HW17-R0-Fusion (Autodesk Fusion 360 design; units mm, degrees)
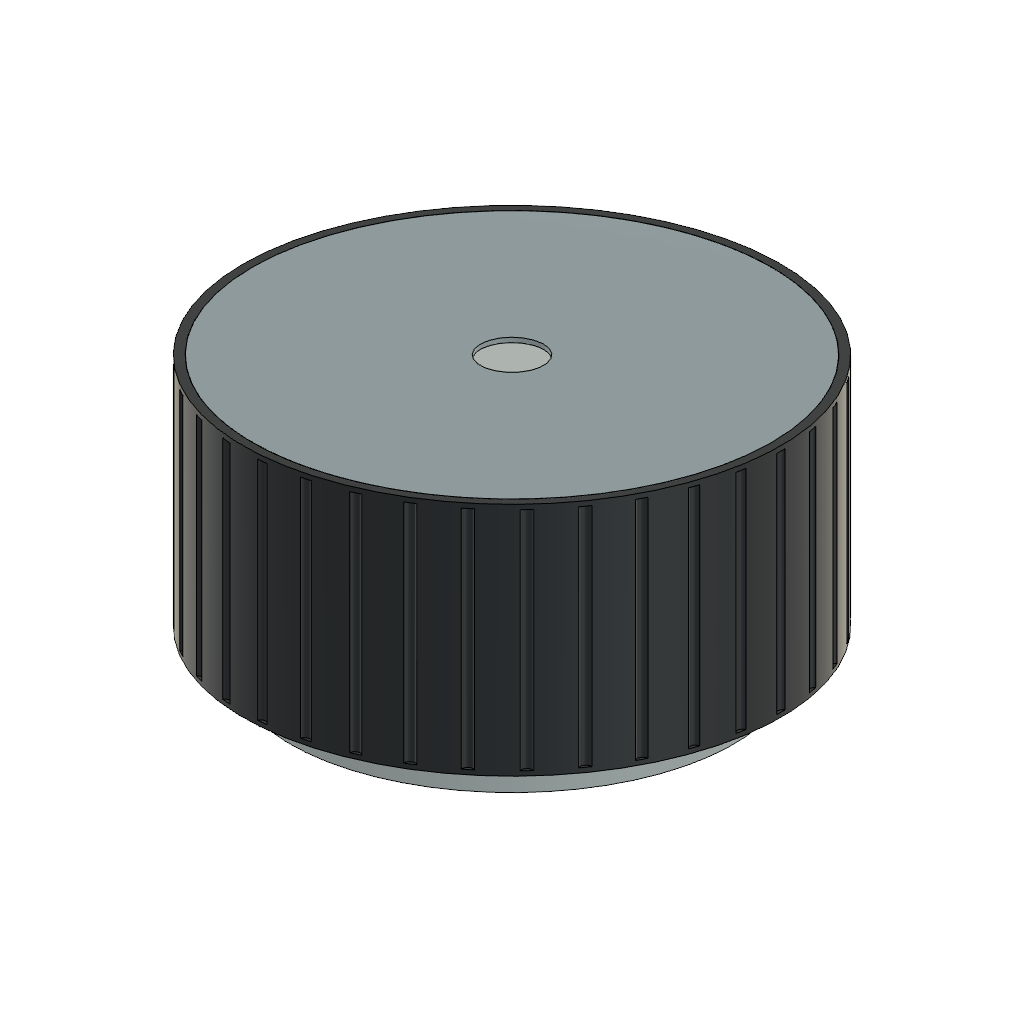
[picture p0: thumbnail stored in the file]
description: Part Number
part number: 2026-10-29-11-14-16-184
part number: 2026-10-29-11-14-16-256
part number: 2026-10-29-11-14-16-259
description: POM | 36 shallow axial flutes, max OD17; black matte finish
part number: HW17-R0-01_grip_ring
part number: HW17-R0-02_rotor_back_iron
part number: HW17-R0-03_rotor_cap
part number: HW17-R0-04_rotor_shaft
part number: HW17-R0-05_magnet_01_N
part number: HW17-R0-05_magnet_02_S
part number: HW17-R0-05_magnet_03_N
part number: HW17-R0-05_magnet_04_S
parameter "grip_od_mm" = 17 comment "R0 geometry source; see build script for dependent sketch geometry"
parameter "grip_id_mm" = 16.4 comment "R0 geometry source; see build script for dependent sketch geometry"
parameter "rotor_bottom_z_mm" = 1.2 comment "R0 geometry source; see build script for dependent sketch geometry"
parameter "top_z_mm" = 8.8 comment "R0 geometry source; see build script for dependent sketch geometry"
parameter "rotor_yoke_id_mm" = 15.4 comment "R0 geometry source; see build script for dependent sketch geometry"
parameter "rotor_yoke_top_z_mm" = 8 comment "R0 geometry source; see build script for dependent sketch geometry"
parameter "cap_spigot_od_mm" = 15.36 comment "R0 geometry source; see build script for dependent sketch geometry"
parameter "cap_spigot_id_mm" = 14 comment "R0 geometry source; see build script for dependent sketch geometry"
parameter "cap_spigot_bottom_z_mm" = 7.4 comment "R0 geometry source; see build script for dependent sketch geometry"
parameter "magnet_od_mm" = 15.3 comment "R0 geometry source; see build script for dependent sketch geometry"
parameter "magnet_id_mm" = 13.5 comment "R0 geometry source; see build script for dependent sketch geometry"
parameter "magnet_bottom_z_mm" = 2.05 comment "R0 geometry source; see build script for dependent sketch geometry"
parameter "magnet_height_mm" = 4.5 comment "R0 geometry source; see build script for dependent sketch geometry"
parameter "stator_od_mm" = 13 comment "R0 geometry source; see build script for dependent sketch geometry"
parameter "stator_id_mm" = 6.1 comment "R0 geometry source; see build script for dependent sketch geometry"
parameter "stator_yoke_od_mm" = 8 comment "R0 geometry source; see build script for dependent sketch geometry"
parameter "stator_bottom_z_mm" = 2.3 comment "R0 geometry source; see build script for dependent sketch geometry"
parameter "stator_stack_mm" = 4 comment "R0 geometry source; see build script for dependent sketch geometry"
parameter "lamination_mm" = 0.2 comment "R0 geometry source; see build script for dependent sketch geometry"
parameter "tooth_width_mm" = 0.8 comment "R0 geometry source; see build script for dependent sketch geometry"
parameter "tooth_tip_root_radius_mm" = 6.1 comment "R0 geometry source; see build script for dependent sketch geometry"
parameter "coil_r_min_mm" = 4.2 comment "R0 geometry source; see build script for dependent sketch geometry"
parameter "coil_r_max_mm" = 5.95 comment "R0 geometry source; see build script for dependent sketch geometry"
parameter "coil_half_width_mm" = 0.98 comment "R0 geometry source; see build script for dependent sketch geometry"
parameter "coil_inner_half_width_mm" = 0.5 comment "R0 geometry source; see build script for dependent sketch geometry"
parameter "coil_bottom_z_mm" = 1.72 comment "R0 geometry source; see build script for dependent sketch geometry"
parameter "coil_top_z_mm" = 6.88 comment "R0 geometry source; see build script for dependent sketch geometry"
parameter "carrier_base_od_mm" = 14 comment "R0 geometry source; see build script for dependent sketch geometry"
parameter "carrier_base_thickness_mm" = 0.6 comment "R0 geometry source; see build script for dependent sketch geometry"
parameter "carrier_post_od_mm" = 6 comment "R0 geometry source; see build script for dependent sketch geometry"
parameter "bearing_od_mm" = 5 comment "R0 geometry source; see build script for dependent sketch geometry"
parameter "bearing_id_mm" = 2 comment "R0 geometry source; see build script for dependent sketch geometry"
parameter "bearing_width_mm" = 2.5 comment "R0 geometry source; see build script for dependent sketch geometry"
parameter "bearing_lower_z_mm" = 2.7 comment "R0 geometry source; see build script for dependent sketch geometry"
parameter "bearing_upper_z_mm" = 5.3 comment "R0 geometry source; see build script for dependent sketch geometry"
parameter "bearing_outer_stop_id_mm" = 4.5 comment "R0 geometry source; see build script for dependent sketch geometry"
parameter "bearing_inner_abutment_od_mm" = 2.6 comment "R0 geometry source; see build script for dependent sketch geometry"
parameter "mount_pcd_mm" = 10.8 comment "R0 geometry source; see build script for dependent sketch geometry"
parameter "mount_boss_od_mm" = 2.4 comment "R0 geometry source; see build script for dependent sketch geometry"
parameter "mount_boss_top_z_mm" = 1.5 comment "R0 geometry source; see build script for dependent sketch geometry"
parameter "mount_pilot_diameter_mm" = 1.1 comment "R0 geometry source; see build script for dependent sketch geometry"
parameter "sensor_pcb_od_mm" = 5.5 comment "R0 geometry source; see build script for dependent sketch geometry"
parameter "sensor_pcb_thickness_mm" = 0.4 comment "R0 geometry source; see build script for dependent sketch geometry"
parameter "sensor_pocket_od_mm" = 5.6 comment "R0 geometry source; see build script for dependent sketch geometry"
parameter "sensor_solder_z_mm" = 0.05 comment "R0 geometry source; see build script for dependent sketch geometry"
parameter "sensor_magnet_od_mm" = 4 comment "R0 geometry source; see build script for dependent sketch geometry"
parameter "sensor_magnet_height_mm" = 0.5 comment "R0 geometry source; see build script for dependent sketch geometry"
parameter "sensor_magnet_bottom_z_mm" = 1.88 comment "R0 geometry source; see build script for dependent sketch geometry"
parameter "case_base_y_mm" = 2.5 comment "R0 geometry source; see build script for dependent sketch geometry"
sketch "Sketch1" plane through (0, 0, 0) normal (0, 0, 1) x axis (1, 0, 0)
  circle C1 centre (0, 0) radius 8.5
  circle C2 centre (0, 0) radius 8.2
  dimension "d50" diameter C1 = 17 (= "2 * ( grip_od_mm / 2 )")
  dimension "d51" diameter C2 = 16.4 (= "2 * ( grip_id_mm / 2 )")
extrude "Extrude1" new body sketch "Sketch1" blind 7.6 (= "top_z_mm - rotor_bottom_z_mm") from offset 1.2 (= "rotor_bottom_z_mm") bodies "01_grip_ring"
sketch "Sketch2" plane through (0, 0, 0) normal (0, 0, 1) x axis (1, 0, 0)
  circle C1 centre (8.56, 0) radius 0.18
  circle C2 centre (8.43, 1.4864) radius 0.18
  circle C3 centre (8.0438, 2.9277) radius 0.18
  circle C4 centre (7.4132, 4.28) radius 0.18
  circle C5 centre (6.5573, 5.5023) radius 0.18
  circle C6 centre (5.5023, 6.5573) radius 0.18
  circle C7 centre (4.28, 7.4132) radius 0.18
  circle C8 centre (2.9277, 8.0438) radius 0.18
  circle C9 centre (1.4864, 8.43) radius 0.18
  circle C10 centre (0, 8.56) radius 0.18
  circle C11 centre (-1.4864, 8.43) radius 0.18
  circle C12 centre (-2.9277, 8.0438) radius 0.18
  circle C13 centre (-4.28, 7.4132) radius 0.18
  circle C14 centre (-5.5023, 6.5573) radius 0.18
  circle C15 centre (-6.5573, 5.5023) radius 0.18
  circle C16 centre (-7.4132, 4.28) radius 0.18
  circle C17 centre (-8.0438, 2.9277) radius 0.18
  circle C18 centre (-8.43, 1.4864) radius 0.18
  circle C19 centre (-8.56, 0) radius 0.18
  circle C20 centre (-8.43, -1.4864) radius 0.18
  circle C21 centre (-8.0438, -2.9277) radius 0.18
  circle C22 centre (-7.4132, -4.28) radius 0.18
  circle C23 centre (-6.5573, -5.5023) radius 0.18
  circle C24 centre (-5.5023, -6.5573) radius 0.18
  circle C25 centre (-4.28, -7.4132) radius 0.18
  circle C26 centre (-2.9277, -8.0438) radius 0.18
  circle C27 centre (-1.4864, -8.43) radius 0.18
  circle C28 centre (0, -8.56) radius 0.18
  circle C29 centre (1.4864, -8.43) radius 0.18
  circle C30 centre (2.9277, -8.0438) radius 0.18
  circle C31 centre (4.28, -7.4132) radius 0.18
  circle C32 centre (5.5023, -6.5573) radius 0.18
  circle C33 centre (6.5573, -5.5023) radius 0.18
  circle C34 centre (7.4132, -4.28) radius 0.18
  circle C35 centre (8.0438, -2.9277) radius 0.18
  circle C36 centre (8.43, -1.4864) radius 0.18
extrude "Extrude2" cut sketch "Sketch2" blind 7.3 from offset 1.35
place_component sketch "Sketch1"
sketch "Sketch1" plane through (0, 0, 0) normal (0, 0, 1) x axis (1, 0, 0)
  circle C1 centre (0, 0) radius 8.2
  circle C2 centre (0, 0) radius 7.7
  dimension "d58" diameter C1 = 16.4 (= "2 * ( grip_id_mm / 2 )")
  dimension "d59" diameter C2 = 15.4 (= "2 * ( rotor_yoke_id_mm / 2 )")
extrude "Extrude1" new body sketch "Sketch1" blind 6.8 (= "rotor_yoke_top_z_mm - rotor_bottom_z_mm") from offset 1.2 (= "rotor_bottom_z_mm") bodies "02_rotor_back_iron"
sketch "Sketch1" plane through (0, 0, 0) normal (0, 0, 1) x axis (1, 0, 0)
  circle C1 centre (0, 0) radius 8.2
  circle C2 centre (0, 0) radius 1
  dimension "d63" diameter C1 = 16.4 (= "2 * ( grip_id_mm / 2 )")
  dimension "d64" diameter C2 = 2 (= "2 * ( bearing_id_mm / 2 )")
extrude "Extrude1" new body sketch "Sketch1" blind 0.8 (= "top_z_mm - rotor_yoke_top_z_mm") from offset 8 (= "rotor_yoke_top_z_mm") bodies "03_rotor_cap"
sketch "Sketch2" plane through (0, 0, 0) normal (0, 0, 1) x axis (1, 0, 0)
  circle C1 centre (0, 0) radius 7.68
  circle C2 centre (0, 0) radius 7
  dimension "d68" diameter C1 = 15.36 (= "2 * ( cap_spigot_od_mm / 2 )")
  dimension "d69" diameter C2 = 14 (= "2 * ( cap_spigot_id_mm / 2 )")
extrude "Extrude2" add sketch "Sketch2" blind 0.6 (= "rotor_yoke_top_z_mm - cap_spigot_bottom_z_mm") from offset 7.4 (= "cap_spigot_bottom_z_mm")
sketch "Sketch3" plane through (0, 0, 0) normal (0, 0, 1) x axis (1, 0, 0)
  circle C1 centre (0, 0) radius 1.3
  circle C2 centre (0, 0) radius 1
  dimension "d73" diameter C1 = 2.6 (= "2 * ( bearing_inner_abutment_od_mm / 2 )")
  dimension "d74" diameter C2 = 2 (= "2 * ( bearing_id_mm / 2 )")
extrude "Extrude3" add sketch "Sketch3" blind 0.2 (= "rotor_yoke_top_z_mm - bearing_upper_z_mm - bearing_width_mm") from offset 7.8 (= "bearing_upper_z_mm + bearing_width_mm")
sketch "Sketch4" plane through (0, 0, 0) normal (0, 0, 1) x axis (1, 0, 0)
  circle C1 centre (0, 0) radius 3.2
  circle C2 centre (0, 0) radius 1.4
extrude "Extrude4" cut sketch "Sketch4" blind 0.31 from offset 7.79
sketch "Sketch1" plane through (0, 0, 0) normal (0, 0, 1) x axis (1, 0, 0)
  circle C1 centre (0, 0) radius 1
  dimension "d81" diameter C1 = 2 (= "2 * ( bearing_id_mm / 2 )")
extrude "Extrude1" new body sketch "Sketch1" blind 5.95 (= "top_z_mm - 0.15 mm - bearing_lower_z_mm") from offset 2.7 (= "bearing_lower_z_mm") bodies "04_rotor_shaft"
sketch "Sketch2" plane through (0, 0, 0) normal (0, 0, 1) x axis (1, 0, 0)
  circle C1 centre (0, 0) radius 1.3
  dimension "d85" diameter C1 = 2.6 (= "2 * ( bearing_inner_abutment_od_mm / 2 )")
extrude "Extrude2" add sketch "Sketch2" blind 0.3 from offset 2.4 (= "bearing_lower_z_mm - 0.3 mm")
place_component sketch "Sketch1"
sketch "Sketch1" plane through (0, 0, 0) normal (0, 0, 1) x axis (1, 0, 0)
  line L1 (6.5885, -1.4675) -> (7.467, -1.6632)
  line L2 (6.5885, 1.4675) -> (7.467, 1.6632)
  arc A1 centre (0, 0) radius 7.65 clockwise from (7.467, 1.6632) to (7.467, -1.6632)
  arc A2 centre (0, 0) radius 6.75 clockwise from (6.5885, 1.4675) to (6.5885, -1.4675)
extrude "Extrude1" new body sketch "Sketch1" blind 4.5 (= "magnet_height_mm") from offset 2.05 (= "magnet_bottom_z_mm") bodies "05_magnet_01_N"
place_component sketch "Sketch1"
sketch "Sketch1" plane through (0, 0, 0) normal (0, 0, 1) x axis (1, 0, 0)
  line L1 (6.5728, 1.5365) -> (7.4492, 1.7413)
  line L2 (5.2993, 4.1809) -> (6.0059, 4.7383)
  arc A1 centre (0, 0) radius 7.65 clockwise from (6.0059, 4.7383) to (7.4492, 1.7413)
  arc A2 centre (0, 0) radius 6.75 clockwise from (5.2993, 4.1809) to (6.5728, 1.5365)
extrude "Extrude1" new body sketch "Sketch1" blind 4.5 (= "magnet_height_mm") from offset 2.05 (= "magnet_bottom_z_mm") bodies "05_magnet_02_S"
place_component sketch "Sketch1"
sketch "Sketch1" plane through (0, 0, 0) normal (0, 0, 1) x axis (1, 0, 0)
  line L1 (5.2553, 4.2361) -> (5.956, 4.8009)
  line L2 (2.9605, 6.0661) -> (3.3553, 6.8749)
  arc A1 centre (0, 0) radius 7.65 clockwise from (3.3553, 6.8749) to (5.956, 4.8009)
  arc A2 centre (0, 0) radius 6.75 clockwise from (2.9605, 6.0661) to (5.2553, 4.2361)
extrude "Extrude1" new body sketch "Sketch1" blind 4.5 (= "magnet_height_mm") from offset 2.05 (= "magnet_bottom_z_mm") bodies "05_magnet_03_N"
place_component sketch "Sketch1"
sketch "Sketch1" plane through (0, 0, 0) normal (0, 0, 1) x axis (1, 0, 0)
  line L1 (2.8968, 6.0968) -> (3.2831, 6.9097)
  line L2 (0.0353, 6.7499) -> (0.0401, 7.6499)
  arc A1 centre (0, 0) radius 7.65 clockwise from (0.0401, 7.6499) to (3.2831, 6.9097)
  arc A2 centre (0, 0) radius 6.75 clockwise from (0.0353, 6.7499) to (2.8968, 6.0968)
extrude "Extrude1" new body sketch "Sketch1" blind 4.5 (= "magnet_height_mm") from offset 2.05 (= "magnet_bottom_z_mm") bodies "05_magnet_04_S"
place_component sketch "Sketch1"
sketch "Sketch1" plane through (0, 0, 0) normal (0, 0, 1) x axis (1, 0, 0)
  line L1 (-0.0353, 6.7499) -> (-0.0401, 7.6499)
  line L2 (-2.8968, 6.0968) -> (-3.2831, 6.9097)
  arc A1 centre (0, 0) radius 7.65 clockwise from (-3.2831, 6.9097) to (-0.0401, 7.6499)
  arc A2 centre (0, 0) radius 6.75 clockwise from (-2.8968, 6.0968) to (-0.0353, 6.7499)
extrude "Extrude1" new body sketch "Sketch1" blind 4.5 (= "magnet_height_mm") from offset 2.05 (= "magnet_bottom_z_mm") bodies "05_magnet_05_N"
place_component sketch "Sketch1"
sketch "Sketch1" plane through (0, 0, 0) normal (0, 0, 1) x axis (1, 0, 0)
  line L1 (-2.9605, 6.0661) -> (-3.3553, 6.8749)
  line L2 (-5.2553, 4.2361) -> (-5.956, 4.8009)
  arc A1 centre (0, 0) radius 7.65 clockwise from (-5.956, 4.8009) to (-3.3553, 6.8749)
  arc A2 centre (0, 0) radius 6.75 clockwise from (-5.2553, 4.2361) to (-2.9605, 6.0661)
extrude "Extrude1" new body sketch "Sketch1" blind 4.5 (= "magnet_height_mm") from offset 2.05 (= "magnet_bottom_z_mm") bodies "05_magnet_06_S"
place_component sketch "Sketch1"
sketch "Sketch1" plane through (0, 0, 0) normal (0, 0, 1) x axis (1, 0, 0)
  line L1 (-5.2993, 4.1809) -> (-6.0059, 4.7383)
  line L2 (-6.5728, 1.5365) -> (-7.4492, 1.7413)
  arc A1 centre (0, 0) radius 7.65 clockwise from (-7.4492, 1.7413) to (-6.0059, 4.7383)
  arc A2 centre (0, 0) radius 6.75 clockwise from (-6.5728, 1.5365) to (-5.2993, 4.1809)
extrude "Extrude1" new body sketch "Sketch1" blind 4.5 (= "magnet_height_mm") from offset 2.05 (= "magnet_bottom_z_mm") bodies "05_magnet_07_N"
place_component sketch "Sketch1"
sketch "Sketch1" plane through (0, 0, 0) normal (0, 0, 1) x axis (1, 0, 0)
  line L1 (-6.5885, 1.4675) -> (-7.467, 1.6632)
  line L2 (-6.5885, -1.4675) -> (-7.467, -1.6632)
  arc A1 centre (0, 0) radius 7.65 clockwise from (-7.467, -1.6632) to (-7.467, 1.6632)
  arc A2 centre (0, 0) radius 6.75 clockwise from (-6.5885, -1.4675) to (-6.5885, 1.4675)
extrude "Extrude1" new body sketch "Sketch1" blind 4.5 (= "magnet_height_mm") from offset 2.05 (= "magnet_bottom_z_mm") bodies "05_magnet_08_S"
place_component sketch "Sketch1"
sketch "Sketch1" plane through (0, 0, 0) normal (0, 0, 1) x axis (1, 0, 0)
  line L1 (-6.5728, -1.5365) -> (-7.4492, -1.7413)
  line L2 (-5.2993, -4.1809) -> (-6.0059, -4.7383)
  arc A1 centre (0, 0) radius 7.65 clockwise from (-6.0059, -4.7383) to (-7.4492, -1.7413)
  arc A2 centre (0, 0) radius 6.75 clockwise from (-5.2993, -4.1809) to (-6.5728, -1.5365)
extrude "Extrude1" new body sketch "Sketch1" blind 4.5 (= "magnet_height_mm") from offset 2.05 (= "magnet_bottom_z_mm") bodies "05_magnet_09_N"
place_component sketch "Sketch1"
sketch "Sketch1" plane through (0, 0, 0) normal (0, 0, 1) x axis (1, 0, 0)
  line L1 (-5.2553, -4.2361) -> (-5.956, -4.8009)
  line L2 (-2.9605, -6.0661) -> (-3.3553, -6.8749)
  arc A1 centre (0, 0) radius 7.65 clockwise from (-3.3553, -6.8749) to (-5.956, -4.8009)
  arc A2 centre (0, 0) radius 6.75 clockwise from (-2.9605, -6.0661) to (-5.2553, -4.2361)
extrude "Extrude1" new body sketch "Sketch1" blind 4.5 (= "magnet_height_mm") from offset 2.05 (= "magnet_bottom_z_mm") bodies "05_magnet_10_S"
place_component sketch "Sketch1"
sketch "Sketch1" plane through (0, 0, 0) normal (0, 0, 1) x axis (1, 0, 0)
  line L1 (-2.8968, -6.0968) -> (-3.2831, -6.9097)
  line L2 (-0.0353, -6.7499) -> (-0.0401, -7.6499)
  arc A1 centre (0, 0) radius 7.65 clockwise from (-0.0401, -7.6499) to (-3.2831, -6.9097)
  arc A2 centre (0, 0) radius 6.75 clockwise from (-0.0353, -6.7499) to (-2.8968, -6.0968)
extrude "Extrude1" new body sketch "Sketch1" blind 4.5 (= "magnet_height_mm") from offset 2.05 (= "magnet_bottom_z_mm") bodies "05_magnet_11_N"
place_component sketch "Sketch1"
sketch "Sketch1" plane through (0, 0, 0) normal (0, 0, 1) x axis (1, 0, 0)
  line L1 (0.0353, -6.7499) -> (0.0401, -7.6499)
  line L2 (2.8968, -6.0968) -> (3.2831, -6.9097)
  arc A1 centre (0, 0) radius 7.65 clockwise from (3.2831, -6.9097) to (0.0401, -7.6499)
  arc A2 centre (0, 0) radius 6.75 clockwise from (2.8968, -6.0968) to (0.0353, -6.7499)
extrude "Extrude1" new body sketch "Sketch1" blind 4.5 (= "magnet_height_mm") from offset 2.05 (= "magnet_bottom_z_mm") bodies "05_magnet_12_S"
place_component sketch "Sketch1"
sketch "Sketch1" plane through (0, 0, 0) normal (0, 0, 1) x axis (1, 0, 0)
  line L1 (2.9605, -6.0661) -> (3.3553, -6.8749)
  line L2 (5.2553, -4.2361) -> (5.956, -4.8009)
  arc A1 centre (0, 0) radius 7.65 clockwise from (5.956, -4.8009) to (3.3553, -6.8749)
  arc A2 centre (0, 0) radius 6.75 clockwise from (5.2553, -4.2361) to (2.9605, -6.0661)
extrude "Extrude1" new body sketch "Sketch1" blind 4.5 (= "magnet_height_mm") from offset 2.05 (= "magnet_bottom_z_mm") bodies "05_magnet_13_N"
place_component sketch "Sketch1"
sketch "Sketch1" plane through (0, 0, 0) normal (0, 0, 1) x axis (1, 0, 0)
  line L1 (5.2993, -4.1809) -> (6.0059, -4.7383)
  line L2 (6.5728, -1.5365) -> (7.4492, -1.7413)
  arc A1 centre (0, 0) radius 7.65 clockwise from (7.4492, -1.7413) to (6.0059, -4.7383)
  arc A2 centre (0, 0) radius 6.75 clockwise from (6.5728, -1.5365) to (5.2993, -4.1809)
extrude "Extrude1" new body sketch "Sketch1" blind 4.5 (= "magnet_height_mm") from offset 2.05 (= "magnet_bottom_z_mm") bodies "05_magnet_14_S"
sketch "Sketch1" plane through (0, 0, 0) normal (0, 0, 1) x axis (1, 0, 0)
  circle C1 centre (0, 0) radius 7
  dimension "d131" diameter C1 = 14 (= "2 * ( carrier_base_od_mm / 2 )")
extrude "Extrude1" new body sketch "Sketch1" along normal blind 0.6 (= "carrier_base_thickness_mm") bodies "06_stator_carrier"
sketch "Sketch2" plane through (0, 0, 0) normal (0, 0, 1) x axis (1, 0, 0)
  circle C1 centre (0, 0) radius 2.8
  dimension "d135" diameter C1 = 5.6 (= "2 * ( sensor_pocket_od_mm / 2 )")
extrude "Extrude2" cut sketch "Sketch2" blind 0.41 (= "sensor_pcb_thickness_mm + 0.01 mm") from offset -0.01
sketch "Sketch3" plane through (0, 0, 0) normal (0, 0, 1) x axis (1, 0, 0)
  circle C1 centre (0, 0) radius 2.5
  dimension "d139" diameter C1 = 5 (= "2 * ( bearing_od_mm / 2 )")
extrude "Extrude3" cut sketch "Sketch3" blind 0.21 (= "carrier_base_thickness_mm - sensor_pcb_thickness_mm + 0.01 mm") from offset 0.4 (= "sensor_pcb_thickness_mm")
sketch "Sketch4" plane through (0, 0, 0) normal (0, 0, 1) x axis (1, 0, 0)
  circle C1 centre (0, 0) radius 3
  circle C2 centre (0, 0) radius 2.5
  dimension "d143" diameter C1 = 6 (= "2 * ( carrier_post_od_mm / 2 )")
  dimension "d144" diameter C2 = 5 (= "2 * ( bearing_od_mm / 2 )")
extrude "Extrude4" add sketch "Sketch4" blind 7.2 (= "bearing_upper_z_mm + bearing_width_mm - carrier_base_thickness_mm") from offset 0.6 (= "carrier_base_thickness_mm")
sketch "Sketch5" plane through (0, 0, 0) normal (0, 0, 1) x axis (1, 0, 0)
  circle C1 centre (0, 0) radius 2.5
  circle C2 centre (0, 0) radius 2.25
  dimension "d148" diameter C1 = 5 (= "2 * ( bearing_od_mm / 2 )")
  dimension "d149" diameter C2 = 4.5 (= "2 * ( bearing_outer_stop_id_mm / 2 )")
extrude "Extrude5" add sketch "Sketch5" blind 0.1 (= "bearing_upper_z_mm - bearing_lower_z_mm - bearing_width_mm") from offset 5.2 (= "bearing_lower_z_mm + bearing_width_mm")
sketch "Sketch6" plane through (0, 0, 0) normal (0, 0, 1) x axis (1, 0, 0)
  circle C1 centre (4.6765, 2.7) radius 1.2
  dimension "d153" diameter C1 = 2.4 (= "2 * ( mount_boss_od_mm / 2 )")
extrude "Extrude6" add sketch "Sketch6" blind 0.9 (= "mount_boss_top_z_mm - carrier_base_thickness_mm") from offset 0.6 (= "carrier_base_thickness_mm")
sketch "Sketch7" plane through (0, 0, 0) normal (0, 0, 1) x axis (1, 0, 0)
  circle C1 centre (4.6765, 2.7) radius 0.55
  dimension "d157" diameter C1 = 1.1 (= "2 * ( mount_pilot_diameter_mm / 2 )")
extrude "Extrude7" cut sketch "Sketch7" blind 1.26 (= "mount_boss_top_z_mm - 0.24 mm") from offset -0.01
sketch "Sketch8" plane through (0, 0, 0) normal (0, 0, 1) x axis (1, 0, 0)
  circle C1 centre (-4.6765, 2.7) radius 1.2
  dimension "d161" diameter C1 = 2.4 (= "2 * ( mount_boss_od_mm / 2 )")
extrude "Extrude8" add sketch "Sketch8" blind 0.9 (= "mount_boss_top_z_mm - carrier_base_thickness_mm") from offset 0.6 (= "carrier_base_thickness_mm")
sketch "Sketch9" plane through (0, 0, 0) normal (0, 0, 1) x axis (1, 0, 0)
  circle C1 centre (-4.6765, 2.7) radius 0.55
  dimension "d165" diameter C1 = 1.1 (= "2 * ( mount_pilot_diameter_mm / 2 )")
extrude "Extrude9" cut sketch "Sketch9" blind 1.26 (= "mount_boss_top_z_mm - 0.24 mm") from offset -0.01
sketch "Sketch10" plane through (0, 0, 0) normal (0, 0, 1) x axis (1, 0, 0)
  circle C1 centre (0, -5.4) radius 1.2
  dimension "d169" diameter C1 = 2.4 (= "2 * ( mount_boss_od_mm / 2 )")
extrude "Extrude10" add sketch "Sketch10" blind 0.9 (= "mount_boss_top_z_mm - carrier_base_thickness_mm") from offset 0.6 (= "carrier_base_thickness_mm")
sketch "Sketch11" plane through (0, 0, 0) normal (0, 0, 1) x axis (1, 0, 0)
  circle C1 centre (0, -5.4) radius 0.55
  dimension "d173" diameter C1 = 1.1 (= "2 * ( mount_pilot_diameter_mm / 2 )")
extrude "Extrude11" cut sketch "Sketch11" blind 1.26 (= "mount_boss_top_z_mm - 0.24 mm") from offset -0.01
sketch "Sketch12" plane through (0, 0, 0) normal (0, 0, 1) x axis (1, 0, 0)
  line L1 (-4.3134, 5.7276) -> (0.7071, 0.7071)
  line L2 (-5.7276, 4.3134) -> (-4.3134, 5.7276)
  line L3 (-0.7071, -0.7071) -> (-5.7276, 4.3134)
  line L4 (0.7071, 0.7071) -> (-0.7071, -0.7071)
extrude "Extrude12" cut sketch "Sketch12" along normal blind 0.4
sketch "Sketch13" plane through (0, 0, 0) normal (0, 0, 1) x axis (1, 0, 0)
  circle C1 centre (0, 4.7) radius 0.45
extrude "Extrude13" cut sketch "Sketch13" blind 0.62 from offset -0.01
sketch "Sketch1" plane through (0, 0, 0) normal (0, 0, 1) x axis (1, 0, 0)
  circle C1 centre (0, 0) radius 4
  circle C2 centre (0, 0) radius 3.05
  dimension "d183" diameter C1 = 8 (= "2 * ( stator_yoke_od_mm / 2 )")
  dimension "d184" diameter C2 = 6.1 (= "2 * ( stator_id_mm / 2 )")
extrude "Extrude1" new body sketch "Sketch1" blind 4 (= "stator_stack_mm") from offset 2.3 (= "stator_bottom_z_mm") bodies "07_stator_stack"
sketch "Sketch2" plane through (0, 0, 0) normal (0, 0, 1) x axis (1, 0, 0)
  line L1 (6.15, -0.4) -> (3.9, -0.4)
  line L2 (6.15, 0.4) -> (6.15, -0.4)
  line L3 (3.9, 0.4) -> (6.15, 0.4)
  line L4 (3.9, -0.4) -> (3.9, 0.4)
extrude "Extrude2" add sketch "Sketch2" blind 4 (= "stator_stack_mm") from offset 2.3 (= "stator_bottom_z_mm")
sketch "Sketch3" plane through (0, 0, 0) normal (0, 0, 1) x axis (1, 0, 0)
  line L1 (5.9879, -1.1639) -> (6.3806, -1.2403)
  line L2 (5.9879, 1.1639) -> (6.3806, 1.2403)
  arc A1 centre (0, 0) radius 6.5 clockwise from (6.3806, 1.2403) to (6.3806, -1.2403)
  arc A2 centre (0, 0) radius 6.1 clockwise from (5.9879, 1.1639) to (5.9879, -1.1639)
extrude "Extrude3" add sketch "Sketch3" blind 4 (= "stator_stack_mm") from offset 2.3 (= "stator_bottom_z_mm")
sketch "Sketch4" plane through (0, 0, 0) normal (0, 0, 1) x axis (1, 0, 0)
  line L1 (5.5261, 2.7286) -> (3.5775, 1.6036)
  line L2 (5.1261, 3.4214) -> (5.5261, 2.7286)
  line L3 (3.1775, 2.2964) -> (5.1261, 3.4214)
  line L4 (3.5775, 1.6036) -> (3.1775, 2.2964)
extrude "Extrude4" add sketch "Sketch4" blind 4 (= "stator_stack_mm") from offset 2.3 (= "stator_bottom_z_mm")
sketch "Sketch5" plane through (0, 0, 0) normal (0, 0, 1) x axis (1, 0, 0)
  line L1 (5.7677, 1.986) -> (6.1459, 2.1162)
  line L2 (4.6037, 4.002) -> (4.9056, 4.2644)
  arc A1 centre (0, 0) radius 6.5 clockwise from (4.9056, 4.2644) to (6.1459, 2.1162)
  arc A2 centre (0, 0) radius 6.1 clockwise from (4.6037, 4.002) to (5.7677, 1.986)
extrude "Extrude5" add sketch "Sketch5" blind 4 (= "stator_stack_mm") from offset 2.3 (= "stator_bottom_z_mm")
sketch "Sketch6" plane through (0, 0, 0) normal (0, 0, 1) x axis (1, 0, 0)
  line L1 (3.4214, 5.1261) -> (2.2964, 3.1775)
  line L2 (2.7286, 5.5261) -> (3.4214, 5.1261)
  line L3 (1.6036, 3.5775) -> (2.7286, 5.5261)
  line L4 (2.2964, 3.1775) -> (1.6036, 3.5775)
extrude "Extrude6" add sketch "Sketch6" blind 4 (= "stator_stack_mm") from offset 2.3 (= "stator_bottom_z_mm")
sketch "Sketch7" plane through (0, 0, 0) normal (0, 0, 1) x axis (1, 0, 0)
  line L1 (4.002, 4.6037) -> (4.2644, 4.9056)
  line L2 (1.986, 5.7677) -> (2.1162, 6.1459)
  arc A1 centre (0, 0) radius 6.5 clockwise from (2.1162, 6.1459) to (4.2644, 4.9056)
  arc A2 centre (0, 0) radius 6.1 clockwise from (1.986, 5.7677) to (4.002, 4.6037)
extrude "Extrude7" add sketch "Sketch7" blind 4 (= "stator_stack_mm") from offset 2.3 (= "stator_bottom_z_mm")
sketch "Sketch8" plane through (0, 0, 0) normal (0, 0, 1) x axis (1, 0, 0)
  line L1 (0.4, 6.15) -> (0.4, 3.9)
  line L2 (-0.4, 6.15) -> (0.4, 6.15)
  line L3 (-0.4, 3.9) -> (-0.4, 6.15)
  line L4 (0.4, 3.9) -> (-0.4, 3.9)
extrude "Extrude8" add sketch "Sketch8" blind 4 (= "stator_stack_mm") from offset 2.3 (= "stator_bottom_z_mm")
sketch "Sketch9" plane through (0, 0, 0) normal (0, 0, 1) x axis (1, 0, 0)
  line L1 (1.1639, 5.9879) -> (1.2403, 6.3806)
  line L2 (-1.1639, 5.9879) -> (-1.2403, 6.3806)
  arc A1 centre (0, 0) radius 6.5 clockwise from (-1.2403, 6.3806) to (1.2403, 6.3806)
  arc A2 centre (0, 0) radius 6.1 clockwise from (-1.1639, 5.9879) to (1.1639, 5.9879)
extrude "Extrude9" add sketch "Sketch9" blind 4 (= "stator_stack_mm") from offset 2.3 (= "stator_bottom_z_mm")
sketch "Sketch10" plane through (0, 0, 0) normal (0, 0, 1) x axis (1, 0, 0)
  line L1 (-2.7286, 5.5261) -> (-1.6036, 3.5775)
  line L2 (-3.4214, 5.1261) -> (-2.7286, 5.5261)
  line L3 (-2.2964, 3.1775) -> (-3.4214, 5.1261)
  line L4 (-1.6036, 3.5775) -> (-2.2964, 3.1775)
extrude "Extrude10" add sketch "Sketch10" blind 4 (= "stator_stack_mm") from offset 2.3 (= "stator_bottom_z_mm")
sketch "Sketch11" plane through (0, 0, 0) normal (0, 0, 1) x axis (1, 0, 0)
  line L1 (-1.986, 5.7677) -> (-2.1162, 6.1459)
  line L2 (-4.002, 4.6037) -> (-4.2644, 4.9056)
  arc A1 centre (0, 0) radius 6.5 clockwise from (-4.2644, 4.9056) to (-2.1162, 6.1459)
  arc A2 centre (0, 0) radius 6.1 clockwise from (-4.002, 4.6037) to (-1.986, 5.7677)
extrude "Extrude11" add sketch "Sketch11" blind 4 (= "stator_stack_mm") from offset 2.3 (= "stator_bottom_z_mm")
sketch "Sketch12" plane through (0, 0, 0) normal (0, 0, 1) x axis (1, 0, 0)
  line L1 (-5.1261, 3.4214) -> (-3.1775, 2.2964)
  line L2 (-5.5261, 2.7286) -> (-5.1261, 3.4214)
  line L3 (-3.5775, 1.6036) -> (-5.5261, 2.7286)
  line L4 (-3.1775, 2.2964) -> (-3.5775, 1.6036)
extrude "Extrude12" add sketch "Sketch12" blind 4 (= "stator_stack_mm") from offset 2.3 (= "stator_bottom_z_mm")
sketch "Sketch13" plane through (0, 0, 0) normal (0, 0, 1) x axis (1, 0, 0)
  line L1 (-4.6037, 4.002) -> (-4.9056, 4.2644)
  line L2 (-5.7677, 1.986) -> (-6.1459, 2.1162)
  arc A1 centre (0, 0) radius 6.5 clockwise from (-6.1459, 2.1162) to (-4.9056, 4.2644)
  arc A2 centre (0, 0) radius 6.1 clockwise from (-5.7677, 1.986) to (-4.6037, 4.002)
extrude "Extrude13" add sketch "Sketch13" blind 4 (= "stator_stack_mm") from offset 2.3 (= "stator_bottom_z_mm")
sketch "Sketch14" plane through (0, 0, 0) normal (0, 0, 1) x axis (1, 0, 0)
  line L1 (-6.15, 0.4) -> (-3.9, 0.4)
  line L2 (-6.15, -0.4) -> (-6.15, 0.4)
  line L3 (-3.9, -0.4) -> (-6.15, -0.4)
  line L4 (-3.9, 0.4) -> (-3.9, -0.4)
extrude "Extrude14" add sketch "Sketch14" blind 4 (= "stator_stack_mm") from offset 2.3 (= "stator_bottom_z_mm")
sketch "Sketch15" plane through (0, 0, 0) normal (0, 0, 1) x axis (1, 0, 0)
  line L1 (-5.9879, 1.1639) -> (-6.3806, 1.2403)
  line L2 (-5.9879, -1.1639) -> (-6.3806, -1.2403)
  arc A1 centre (0, 0) radius 6.5 clockwise from (-6.3806, -1.2403) to (-6.3806, 1.2403)
  arc A2 centre (0, 0) radius 6.1 clockwise from (-5.9879, -1.1639) to (-5.9879, 1.1639)
extrude "Extrude15" add sketch "Sketch15" blind 4 (= "stator_stack_mm") from offset 2.3 (= "stator_bottom_z_mm")
sketch "Sketch16" plane through (0, 0, 0) normal (0, 0, 1) x axis (1, 0, 0)
  line L1 (-5.5261, -2.7286) -> (-3.5775, -1.6036)
  line L2 (-5.1261, -3.4214) -> (-5.5261, -2.7286)
  line L3 (-3.1775, -2.2964) -> (-5.1261, -3.4214)
  line L4 (-3.5775, -1.6036) -> (-3.1775, -2.2964)
extrude "Extrude16" add sketch "Sketch16" blind 4 (= "stator_stack_mm") from offset 2.3 (= "stator_bottom_z_mm")
sketch "Sketch17" plane through (0, 0, 0) normal (0, 0, 1) x axis (1, 0, 0)
  line L1 (-5.7677, -1.986) -> (-6.1459, -2.1162)
  line L2 (-4.6037, -4.002) -> (-4.9056, -4.2644)
  arc A1 centre (0, 0) radius 6.5 clockwise from (-4.9056, -4.2644) to (-6.1459, -2.1162)
  arc A2 centre (0, 0) radius 6.1 clockwise from (-4.6037, -4.002) to (-5.7677, -1.986)
extrude "Extrude17" add sketch "Sketch17" blind 4 (= "stator_stack_mm") from offset 2.3 (= "stator_bottom_z_mm")
sketch "Sketch18" plane through (0, 0, 0) normal (0, 0, 1) x axis (1, 0, 0)
  line L1 (-3.4214, -5.1261) -> (-2.2964, -3.1775)
  line L2 (-2.7286, -5.5261) -> (-3.4214, -5.1261)
  line L3 (-1.6036, -3.5775) -> (-2.7286, -5.5261)
  line L4 (-2.2964, -3.1775) -> (-1.6036, -3.5775)
extrude "Extrude18" add sketch "Sketch18" blind 4 (= "stator_stack_mm") from offset 2.3 (= "stator_bottom_z_mm")
sketch "Sketch19" plane through (0, 0, 0) normal (0, 0, 1) x axis (1, 0, 0)
  line L1 (-4.002, -4.6037) -> (-4.2644, -4.9056)
  line L2 (-1.986, -5.7677) -> (-2.1162, -6.1459)
  arc A1 centre (0, 0) radius 6.5 clockwise from (-2.1162, -6.1459) to (-4.2644, -4.9056)
  arc A2 centre (0, 0) radius 6.1 clockwise from (-1.986, -5.7677) to (-4.002, -4.6037)
extrude "Extrude19" add sketch "Sketch19" blind 4 (= "stator_stack_mm") from offset 2.3 (= "stator_bottom_z_mm")
sketch "Sketch20" plane through (0, 0, 0) normal (0, 0, 1) x axis (1, 0, 0)
  line L1 (-0.4, -6.15) -> (-0.4, -3.9)
  line L2 (0.4, -6.15) -> (-0.4, -6.15)
  line L3 (0.4, -3.9) -> (0.4, -6.15)
  line L4 (-0.4, -3.9) -> (0.4, -3.9)
extrude "Extrude20" add sketch "Sketch20" blind 4 (= "stator_stack_mm") from offset 2.3 (= "stator_bottom_z_mm")
sketch "Sketch21" plane through (0, 0, 0) normal (0, 0, 1) x axis (1, 0, 0)
  line L1 (-1.1639, -5.9879) -> (-1.2403, -6.3806)
  line L2 (1.1639, -5.9879) -> (1.2403, -6.3806)
  arc A1 centre (0, 0) radius 6.5 clockwise from (1.2403, -6.3806) to (-1.2403, -6.3806)
  arc A2 centre (0, 0) radius 6.1 clockwise from (1.1639, -5.9879) to (-1.1639, -5.9879)
extrude "Extrude21" add sketch "Sketch21" blind 4 (= "stator_stack_mm") from offset 2.3 (= "stator_bottom_z_mm")
sketch "Sketch22" plane through (0, 0, 0) normal (0, 0, 1) x axis (1, 0, 0)
  line L1 (2.7286, -5.5261) -> (1.6036, -3.5775)
  line L2 (3.4214, -5.1261) -> (2.7286, -5.5261)
  line L3 (2.2964, -3.1775) -> (3.4214, -5.1261)
  line L4 (1.6036, -3.5775) -> (2.2964, -3.1775)
extrude "Extrude22" add sketch "Sketch22" blind 4 (= "stator_stack_mm") from offset 2.3 (= "stator_bottom_z_mm")
sketch "Sketch23" plane through (0, 0, 0) normal (0, 0, 1) x axis (1, 0, 0)
  line L1 (1.986, -5.7677) -> (2.1162, -6.1459)
  line L2 (4.002, -4.6037) -> (4.2644, -4.9056)
  arc A1 centre (0, 0) radius 6.5 clockwise from (4.2644, -4.9056) to (2.1162, -6.1459)
  arc A2 centre (0, 0) radius 6.1 clockwise from (4.002, -4.6037) to (1.986, -5.7677)
extrude "Extrude23" add sketch "Sketch23" blind 4 (= "stator_stack_mm") from offset 2.3 (= "stator_bottom_z_mm")
sketch "Sketch24" plane through (0, 0, 0) normal (0, 0, 1) x axis (1, 0, 0)
  line L1 (5.1261, -3.4214) -> (3.1775, -2.2964)
  line L2 (5.5261, -2.7286) -> (5.1261, -3.4214)
  line L3 (3.5775, -1.6036) -> (5.5261, -2.7286)
  line L4 (3.1775, -2.2964) -> (3.5775, -1.6036)
extrude "Extrude24" add sketch "Sketch24" blind 4 (= "stator_stack_mm") from offset 2.3 (= "stator_bottom_z_mm")
sketch "Sketch25" plane through (0, 0, 0) normal (0, 0, 1) x axis (1, 0, 0)
  line L1 (4.6037, -4.002) -> (4.9056, -4.2644)
  line L2 (5.7677, -1.986) -> (6.1459, -2.1162)
  arc A1 centre (0, 0) radius 6.5 clockwise from (6.1459, -2.1162) to (4.9056, -4.2644)
  arc A2 centre (0, 0) radius 6.1 clockwise from (5.7677, -1.986) to (4.6037, -4.002)
extrude "Extrude25" add sketch "Sketch25" blind 4 (= "stator_stack_mm") from offset 2.3 (= "stator_bottom_z_mm")
sketch "Sketch1" plane through (0, 0, 0) normal (0, 0, 1) x axis (1, 0, 0)
  line L1 (5.95, -0.98) -> (4.2, -0.98)
  line L2 (5.95, 0.98) -> (5.95, -0.98)
  line L3 (4.2, 0.98) -> (5.95, 0.98)
  line L4 (4.2, -0.98) -> (4.2, 0.98)
extrude "Extrude1" new body sketch "Sketch1" blind 5.16 (= "coil_top_z_mm - coil_bottom_z_mm") from offset 1.72 (= "coil_bottom_z_mm") bodies "08_coil_01_Ap"
sketch "Sketch2" plane through (0, 0, 0) normal (0, 0, 1) x axis (1, 0, 0)
  line L1 (5.96, -0.5) -> (4.19, -0.5)
  line L2 (5.96, 0.5) -> (5.96, -0.5)
  line L3 (4.19, 0.5) -> (5.96, 0.5)
  line L4 (4.19, -0.5) -> (4.19, 0.5)
extrude "Extrude2" cut sketch "Sketch2" blind 4.2 (= "stator_stack_mm + 0.2 mm") from offset 2.2 (= "stator_bottom_z_mm - 0.1 mm")
sketch "Sketch1" plane through (0, 0, 0) normal (0, 0, 1) x axis (1, 0, 0)
  line L1 (5.6429, 2.1263) -> (4.1273, 1.2513)
  line L2 (4.6629, 3.8237) -> (5.6429, 2.1263)
  line L3 (3.1473, 2.9487) -> (4.6629, 3.8237)
  line L4 (4.1273, 1.2513) -> (3.1473, 2.9487)
extrude "Extrude1" new body sketch "Sketch1" blind 5.16 (= "coil_top_z_mm - coil_bottom_z_mm") from offset 1.72 (= "coil_bottom_z_mm") bodies "08_coil_02_An"
sketch "Sketch2" plane through (0, 0, 0) normal (0, 0, 1) x axis (1, 0, 0)
  line L1 (5.4115, 2.547) -> (3.8786, 1.662)
  line L2 (4.9115, 3.413) -> (5.4115, 2.547)
  line L3 (3.3786, 2.528) -> (4.9115, 3.413)
  line L4 (3.8786, 1.662) -> (3.3786, 2.528)
extrude "Extrude2" cut sketch "Sketch2" blind 4.2 (= "stator_stack_mm + 0.2 mm") from offset 2.2 (= "stator_bottom_z_mm - 0.1 mm")
sketch "Sketch1" plane through (0, 0, 0) normal (0, 0, 1) x axis (1, 0, 0)
  line L1 (3.8237, 4.6629) -> (2.9487, 3.1473)
  line L2 (2.1263, 5.6429) -> (3.8237, 4.6629)
  line L3 (1.2513, 4.1273) -> (2.1263, 5.6429)
  line L4 (2.9487, 3.1473) -> (1.2513, 4.1273)
extrude "Extrude1" new body sketch "Sketch1" blind 5.16 (= "coil_top_z_mm - coil_bottom_z_mm") from offset 1.72 (= "coil_bottom_z_mm") bodies "08_coil_03_Bn"
sketch "Sketch2" plane through (0, 0, 0) normal (0, 0, 1) x axis (1, 0, 0)
  line L1 (3.413, 4.9115) -> (2.528, 3.3786)
  line L2 (2.547, 5.4115) -> (3.413, 4.9115)
  line L3 (1.662, 3.8786) -> (2.547, 5.4115)
  line L4 (2.528, 3.3786) -> (1.662, 3.8786)
extrude "Extrude2" cut sketch "Sketch2" blind 4.2 (= "stator_stack_mm + 0.2 mm") from offset 2.2 (= "stator_bottom_z_mm - 0.1 mm")
sketch "Sketch1" plane through (0, 0, 0) normal (0, 0, 1) x axis (1, 0, 0)
  line L1 (0.98, 5.95) -> (0.98, 4.2)
  line L2 (-0.98, 5.95) -> (0.98, 5.95)
  line L3 (-0.98, 4.2) -> (-0.98, 5.95)
  line L4 (0.98, 4.2) -> (-0.98, 4.2)
extrude "Extrude1" new body sketch "Sketch1" blind 5.16 (= "coil_top_z_mm - coil_bottom_z_mm") from offset 1.72 (= "coil_bottom_z_mm") bodies "08_coil_04_Bp"
sketch "Sketch2" plane through (0, 0, 0) normal (0, 0, 1) x axis (1, 0, 0)
  line L1 (0.5, 5.96) -> (0.5, 4.19)
  line L2 (-0.5, 5.96) -> (0.5, 5.96)
  line L3 (-0.5, 4.19) -> (-0.5, 5.96)
  line L4 (0.5, 4.19) -> (-0.5, 4.19)
extrude "Extrude2" cut sketch "Sketch2" blind 4.2 (= "stator_stack_mm + 0.2 mm") from offset 2.2 (= "stator_bottom_z_mm - 0.1 mm")
sketch "Sketch1" plane through (0, 0, 0) normal (0, 0, 1) x axis (1, 0, 0)
  line L1 (-2.1263, 5.6429) -> (-1.2513, 4.1273)
  line L2 (-3.8237, 4.6629) -> (-2.1263, 5.6429)
  line L3 (-2.9487, 3.1473) -> (-3.8237, 4.6629)
  line L4 (-1.2513, 4.1273) -> (-2.9487, 3.1473)
extrude "Extrude1" new body sketch "Sketch1" blind 5.16 (= "coil_top_z_mm - coil_bottom_z_mm") from offset 1.72 (= "coil_bottom_z_mm") bodies "08_coil_05_Cp"
sketch "Sketch2" plane through (0, 0, 0) normal (0, 0, 1) x axis (1, 0, 0)
  line L1 (-2.547, 5.4115) -> (-1.662, 3.8786)
  line L2 (-3.413, 4.9115) -> (-2.547, 5.4115)
  line L3 (-2.528, 3.3786) -> (-3.413, 4.9115)
  line L4 (-1.662, 3.8786) -> (-2.528, 3.3786)
extrude "Extrude2" cut sketch "Sketch2" blind 4.2 (= "stator_stack_mm + 0.2 mm") from offset 2.2 (= "stator_bottom_z_mm - 0.1 mm")
sketch "Sketch1" plane through (0, 0, 0) normal (0, 0, 1) x axis (1, 0, 0)
  line L1 (-4.6629, 3.8237) -> (-3.1473, 2.9487)
  line L2 (-5.6429, 2.1263) -> (-4.6629, 3.8237)
  line L3 (-4.1273, 1.2513) -> (-5.6429, 2.1263)
  line L4 (-3.1473, 2.9487) -> (-4.1273, 1.2513)
extrude "Extrude1" new body sketch "Sketch1" blind 5.16 (= "coil_top_z_mm - coil_bottom_z_mm") from offset 1.72 (= "coil_bottom_z_mm") bodies "08_coil_06_Cn"
sketch "Sketch2" plane through (0, 0, 0) normal (0, 0, 1) x axis (1, 0, 0)
  line L1 (-4.9115, 3.413) -> (-3.3786, 2.528)
  line L2 (-5.4115, 2.547) -> (-4.9115, 3.413)
  line L3 (-3.8786, 1.662) -> (-5.4115, 2.547)
  line L4 (-3.3786, 2.528) -> (-3.8786, 1.662)
extrude "Extrude2" cut sketch "Sketch2" blind 4.2 (= "stator_stack_mm + 0.2 mm") from offset 2.2 (= "stator_bottom_z_mm - 0.1 mm")
sketch "Sketch1" plane through (0, 0, 0) normal (0, 0, 1) x axis (1, 0, 0)
  line L1 (-5.95, 0.98) -> (-4.2, 0.98)
  line L2 (-5.95, -0.98) -> (-5.95, 0.98)
  line L3 (-4.2, -0.98) -> (-5.95, -0.98)
  line L4 (-4.2, 0.98) -> (-4.2, -0.98)
extrude "Extrude1" new body sketch "Sketch1" blind 5.16 (= "coil_top_z_mm - coil_bottom_z_mm") from offset 1.72 (= "coil_bottom_z_mm") bodies "08_coil_07_An"
sketch "Sketch2" plane through (0, 0, 0) normal (0, 0, 1) x axis (1, 0, 0)
  line L1 (-5.96, 0.5) -> (-4.19, 0.5)
  line L2 (-5.96, -0.5) -> (-5.96, 0.5)
  line L3 (-4.19, -0.5) -> (-5.96, -0.5)
  line L4 (-4.19, 0.5) -> (-4.19, -0.5)
extrude "Extrude2" cut sketch "Sketch2" blind 4.2 (= "stator_stack_mm + 0.2 mm") from offset 2.2 (= "stator_bottom_z_mm - 0.1 mm")
sketch "Sketch1" plane through (0, 0, 0) normal (0, 0, 1) x axis (1, 0, 0)
  line L1 (-5.6429, -2.1263) -> (-4.1273, -1.2513)
  line L2 (-4.6629, -3.8237) -> (-5.6429, -2.1263)
  line L3 (-3.1473, -2.9487) -> (-4.6629, -3.8237)
  line L4 (-4.1273, -1.2513) -> (-3.1473, -2.9487)
extrude "Extrude1" new body sketch "Sketch1" blind 5.16 (= "coil_top_z_mm - coil_bottom_z_mm") from offset 1.72 (= "coil_bottom_z_mm") bodies "08_coil_08_Ap"
sketch "Sketch2" plane through (0, 0, 0) normal (0, 0, 1) x axis (1, 0, 0)
  line L1 (-5.4115, -2.547) -> (-3.8786, -1.662)
  line L2 (-4.9115, -3.413) -> (-5.4115, -2.547)
  line L3 (-3.3786, -2.528) -> (-4.9115, -3.413)
  line L4 (-3.8786, -1.662) -> (-3.3786, -2.528)
extrude "Extrude2" cut sketch "Sketch2" blind 4.2 (= "stator_stack_mm + 0.2 mm") from offset 2.2 (= "stator_bottom_z_mm - 0.1 mm")
sketch "Sketch1" plane through (0, 0, 0) normal (0, 0, 1) x axis (1, 0, 0)
  line L1 (-3.8237, -4.6629) -> (-2.9487, -3.1473)
  line L2 (-2.1263, -5.6429) -> (-3.8237, -4.6629)
  line L3 (-1.2513, -4.1273) -> (-2.1263, -5.6429)
  line L4 (-2.9487, -3.1473) -> (-1.2513, -4.1273)
extrude "Extrude1" new body sketch "Sketch1" blind 5.16 (= "coil_top_z_mm - coil_bottom_z_mm") from offset 1.72 (= "coil_bottom_z_mm") bodies "08_coil_09_Bp"
sketch "Sketch2" plane through (0, 0, 0) normal (0, 0, 1) x axis (1, 0, 0)
  line L1 (-3.413, -4.9115) -> (-2.528, -3.3786)
  line L2 (-2.547, -5.4115) -> (-3.413, -4.9115)
  line L3 (-1.662, -3.8786) -> (-2.547, -5.4115)
  line L4 (-2.528, -3.3786) -> (-1.662, -3.8786)
extrude "Extrude2" cut sketch "Sketch2" blind 4.2 (= "stator_stack_mm + 0.2 mm") from offset 2.2 (= "stator_bottom_z_mm - 0.1 mm")
sketch "Sketch1" plane through (0, 0, 0) normal (0, 0, 1) x axis (1, 0, 0)
  line L1 (-0.98, -5.95) -> (-0.98, -4.2)
  line L2 (0.98, -5.95) -> (-0.98, -5.95)
  line L3 (0.98, -4.2) -> (0.98, -5.95)
  line L4 (-0.98, -4.2) -> (0.98, -4.2)
extrude "Extrude1" new body sketch "Sketch1" blind 5.16 (= "coil_top_z_mm - coil_bottom_z_mm") from offset 1.72 (= "coil_bottom_z_mm") bodies "08_coil_10_Bn"
sketch "Sketch2" plane through (0, 0, 0) normal (0, 0, 1) x axis (1, 0, 0)
  line L1 (-0.5, -5.96) -> (-0.5, -4.19)
  line L2 (0.5, -5.96) -> (-0.5, -5.96)
  line L3 (0.5, -4.19) -> (0.5, -5.96)
  line L4 (-0.5, -4.19) -> (0.5, -4.19)
extrude "Extrude2" cut sketch "Sketch2" blind 4.2 (= "stator_stack_mm + 0.2 mm") from offset 2.2 (= "stator_bottom_z_mm - 0.1 mm")
sketch "Sketch1" plane through (0, 0, 0) normal (0, 0, 1) x axis (1, 0, 0)
  line L1 (2.1263, -5.6429) -> (1.2513, -4.1273)
  line L2 (3.8237, -4.6629) -> (2.1263, -5.6429)
  line L3 (2.9487, -3.1473) -> (3.8237, -4.6629)
  line L4 (1.2513, -4.1273) -> (2.9487, -3.1473)
extrude "Extrude1" new body sketch "Sketch1" blind 5.16 (= "coil_top_z_mm - coil_bottom_z_mm") from offset 1.72 (= "coil_bottom_z_mm") bodies "08_coil_11_Cn"
sketch "Sketch2" plane through (0, 0, 0) normal (0, 0, 1) x axis (1, 0, 0)
  line L1 (2.547, -5.4115) -> (1.662, -3.8786)
  line L2 (3.413, -4.9115) -> (2.547, -5.4115)
  line L3 (2.528, -3.3786) -> (3.413, -4.9115)
  line L4 (1.662, -3.8786) -> (2.528, -3.3786)
extrude "Extrude2" cut sketch "Sketch2" blind 4.2 (= "stator_stack_mm + 0.2 mm") from offset 2.2 (= "stator_bottom_z_mm - 0.1 mm")
sketch "Sketch1" plane through (0, 0, 0) normal (0, 0, 1) x axis (1, 0, 0)
  line L1 (4.6629, -3.8237) -> (3.1473, -2.9487)
  line L2 (5.6429, -2.1263) -> (4.6629, -3.8237)
  line L3 (4.1273, -1.2513) -> (5.6429, -2.1263)
  line L4 (3.1473, -2.9487) -> (4.1273, -1.2513)
extrude "Extrude1" new body sketch "Sketch1" blind 5.16 (= "coil_top_z_mm - coil_bottom_z_mm") from offset 1.72 (= "coil_bottom_z_mm") bodies "08_coil_12_Cp"
sketch "Sketch2" plane through (0, 0, 0) normal (0, 0, 1) x axis (1, 0, 0)
  line L1 (4.9115, -3.413) -> (3.3786, -2.528)
  line L2 (5.4115, -2.547) -> (4.9115, -3.413)
  line L3 (3.8786, -1.662) -> (5.4115, -2.547)
  line L4 (3.3786, -2.528) -> (3.8786, -1.662)
extrude "Extrude2" cut sketch "Sketch2" blind 4.2 (= "stator_stack_mm + 0.2 mm") from offset 2.2 (= "stator_bottom_z_mm - 0.1 mm")
place_component sketch "Sketch1"
sketch "Sketch1" plane through (0, 0, 0) normal (0, 0, 1) x axis (1, 0, 0)
  circle C1 centre (0, 0) radius 2.5
  circle C2 centre (0, 0) radius 1
  dimension "d332" diameter C1 = 5 (= "2 * ( bearing_od_mm / 2 )")
  dimension "d333" diameter C2 = 2 (= "2 * ( bearing_id_mm / 2 )")
extrude "Extrude1" new body sketch "Sketch1" blind 2.5 (= "bearing_width_mm") from offset 2.7 (= "bearing_lower_z_mm") bodies "09_bearing_1"
place_component sketch "Sketch1"
sketch "Sketch1" plane through (0, 0, 0) normal (0, 0, 1) x axis (1, 0, 0)
  circle C1 centre (0, 0) radius 2.5
  circle C2 centre (0, 0) radius 1
  dimension "d337" diameter C1 = 5 (= "2 * ( bearing_od_mm / 2 )")
  dimension "d338" diameter C2 = 2 (= "2 * ( bearing_id_mm / 2 )")
extrude "Extrude1" new body sketch "Sketch1" blind 2.5 (= "bearing_width_mm") from offset 5.3 (= "bearing_upper_z_mm") bodies "09_bearing_2"
place_component sketch "Sketch1"
sketch "Sketch1" plane through (0, 0, 0) normal (0, 0, 1) x axis (1, 0, 0)
  circle C1 centre (0, 0) radius 1.3
  circle C2 centre (0, 0) radius 1
  dimension "d342" diameter C1 = 2.6 (= "2 * ( bearing_inner_abutment_od_mm / 2 )")
  dimension "d343" diameter C2 = 2 (= "2 * ( bearing_id_mm / 2 )")
extrude "Extrude1" new body sketch "Sketch1" blind 0.1 (= "bearing_upper_z_mm - bearing_lower_z_mm - bearing_width_mm") from offset 5.2 (= "bearing_lower_z_mm + bearing_width_mm") bodies "10_inner_spacer"
place_component sketch "Sketch1"
sketch "Sketch1" plane through (0, 0, 0) normal (0, 0, 1) x axis (1, 0, 0)
  circle C1 centre (0, 0) radius 2.5
  circle C2 centre (0, 0) radius 2.25
  dimension "d347" diameter C1 = 5 (= "2 * ( bearing_od_mm / 2 )")
  dimension "d348" diameter C2 = 4.5 (= "2 * ( bearing_outer_stop_id_mm / 2 )")
extrude "Extrude1" new body sketch "Sketch1" blind 0.2 from offset 2.5 (= "bearing_lower_z_mm - 0.2 mm") bodies "11_lower_outer_retainer"
place_component sketch "Sketch1"
sketch "Sketch1" plane through (0, 0, 0) normal (0, 0, 1) x axis (1, 0, 0)
  circle C1 centre (0, 0) radius 2.5
  circle C2 centre (0, 0) radius 2.25
  dimension "d352" diameter C1 = 5 (= "2 * ( bearing_od_mm / 2 )")
  dimension "d353" diameter C2 = 4.5 (= "2 * ( bearing_outer_stop_id_mm / 2 )")
extrude "Extrude1" new body sketch "Sketch1" blind 0.2 from offset 7.8 (= "bearing_upper_z_mm + bearing_width_mm") bodies "12_upper_outer_retainer"
place_component sketch "Sketch1"
sketch "Sketch1" plane through (0, 0, 0) normal (0, 0, 1) x axis (1, 0, 0)
  circle C1 centre (0, 0) radius 2
  dimension "d357" diameter C1 = 4 (= "2 * ( sensor_magnet_od_mm / 2 )")
extrude "Extrude1" new body sketch "Sketch1" blind 0.5 (= "sensor_magnet_height_mm") from offset 1.88 (= "sensor_magnet_bottom_z_mm") bodies "13_sensor_magnet"
sketch "Sketch1" plane through (0, 0, 0) normal (0, 0, 1) x axis (1, 0, 0)
  circle C1 centre (0, 0) radius 2.75
  dimension "d361" diameter C1 = 5.5 (= "2 * ( sensor_pcb_od_mm / 2 )")
extrude "Extrude1" new body sketch "Sketch1" along normal blind 0.4 (= "sensor_pcb_thickness_mm") bodies "14_sensor_flex"
sketch "Sketch2" plane through (0, 0, 0) normal (0, 0, 1) x axis (1, 0, 0)
  line L1 (-4.2426, 5.374) -> (0.5657, 0.5657)
  line L2 (-5.374, 4.2426) -> (-4.2426, 5.374)
  line L3 (-0.5657, -0.5657) -> (-5.374, 4.2426)
  line L4 (0.5657, 0.5657) -> (-0.5657, -0.5657)
extrude "Extrude2" add sketch "Sketch2" along normal blind 0.15
place_component sketch "Sketch1"
sketch "Sketch1" plane through (0, 0, 0) normal (0, 0, 1) x axis (1, 0, 0)
  line L1 (1.55, -1.55) -> (-1.55, -1.55)
  line L2 (1.55, 1.55) -> (1.55, -1.55)
  line L3 (-1.55, 1.55) -> (1.55, 1.55)
  line L4 (-1.55, -1.55) -> (-1.55, 1.55)
extrude "Extrude1" new body sketch "Sketch1" blind 0.8 from offset 0.45 bodies "15_MT6701_max_envelope"
place_component sketch "Sketch1"
sketch "Sketch1" plane through (0, 0, 0) normal (0, 0, 1) x axis (1, 0, 0)
  line L1 (2.25, -0.15) -> (1.65, -0.15)
  line L2 (2.25, 0.15) -> (2.25, -0.15)
  line L3 (1.65, 0.15) -> (2.25, 0.15)
  line L4 (1.65, -0.15) -> (1.65, 0.15)
extrude "Extrude1" new body sketch "Sketch1" blind 0.3 from offset 0.45 bodies "16_sensor_decoupling"
ground "Pin"
as_built_joint "As-built1"
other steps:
create_component "CreateComponent1"
create_component "CreateComponent2"
create_component "CreateComponent1"
create_component "CreateComponent2" sketch "Sketch1"
create_component "CreateComponent3"
create_component "CreateComponent4"
create_component "CreateComponent5" sketch "Sketch1"
create_component "CreateComponent6" sketch "Sketch1"
create_component "CreateComponent7" sketch "Sketch1"
create_component "CreateComponent8" sketch "Sketch1"
create_component "CreateComponent9" sketch "Sketch1"
create_component "CreateComponent10" sketch "Sketch1"
create_component "CreateComponent11" sketch "Sketch1"
create_component "CreateComponent12" sketch "Sketch1"
create_component "CreateComponent13" sketch "Sketch1"
create_component "CreateComponent14" sketch "Sketch1"
create_component "CreateComponent15" sketch "Sketch1"
create_component "CreateComponent16" sketch "Sketch1"
create_component "CreateComponent17" sketch "Sketch1"
create_component "CreateComponent18" sketch "Sketch1"
create_component "CreateComponent1"
create_component "CreateComponent2"
create_component "CreateComponent3"
create_component "CreateComponent4"
create_component "CreateComponent5"
create_component "CreateComponent6"
create_component "CreateComponent7"
create_component "CreateComponent8"
create_component "CreateComponent9"
create_component "CreateComponent10"
create_component "CreateComponent11"
create_component "CreateComponent12"
create_component "CreateComponent13"
create_component "CreateComponent14"
create_component "CreateComponent15" sketch "Sketch1"
create_component "CreateComponent16" sketch "Sketch1"
create_component "CreateComponent19" sketch "Sketch1"
create_component "CreateComponent17" sketch "Sketch1"
create_component "CreateComponent18" sketch "Sketch1"
create_component "CreateComponent20" sketch "Sketch1"
create_component "CreateComponent19"
create_component "CreateComponent20" sketch "Sketch1"
create_component "CreateComponent21" sketch "Sketch1"
named bodies: "01_grip_ring", "02_rotor_back_iron", "03_rotor_cap", "04_rotor_shaft", "05_magnet_01_N", "05_magnet_02_S", "05_magnet_03_N", "05_magnet_04_S", "05_magnet_05_N", "05_magnet_06_S", "05_magnet_07_N", "05_magnet_08_S", "05_magnet_09_N", "05_magnet_10_S", "05_magnet_11_N", "05_magnet_12_S", "05_magnet_13_N", "05_magnet_14_S", "06_stator_carrier", "07_stator_stack", "08_coil_01_Ap", "08_coil_02_An", "08_coil_03_Bn", "08_coil_04_Bp", "08_coil_05_Cp", "08_coil_06_Cn", "08_coil_07_An", "08_coil_08_Ap", "08_coil_09_Bp", "08_coil_10_Bn", "08_coil_11_Cn", "08_coil_12_Cp", "09_bearing_1", "09_bearing_2", "10_inner_spacer", "11_lower_outer_retainer", "12_upper_outer_retainer", "13_sensor_magnet", "14_sensor_flex", "15_MT6701_max_envelope", "16_sensor_decoupling"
